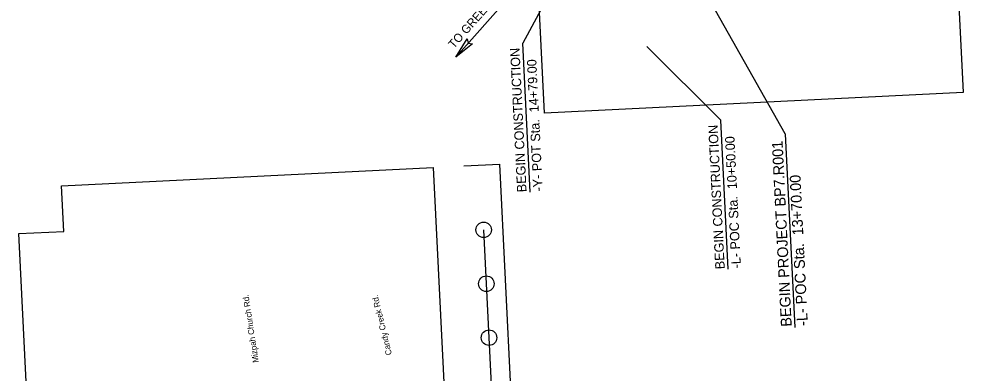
# Model space of a CAD drawing. Extents: x 1805231 to 1809482, y 908883 to 918297.
# Drawn here: x 1805232 to 1808728, y 912434 to 913747 of the extents above; entities that cross this region are included whole.
import ezdxf

# ---------------------------------------------------------------- set-up
doc = ezdxf.new("R2010")
doc.units = 0
for name, color, linetype in [('Default', 7, 'Continuous'), ('Old_Level_40', 7, 'Continuous'), ('Prop DSN Text', 7, 'Continuous'), ('Prop Horizontal Alignment Station Label', 7, 'Continuous'), ('Prop Leader Line Medium', 7, 'Continuous'), ('Prop Terminator CELL', 7, 'Continuous'), ('Scratch_Level_0', 7, 'Continuous')]:
    doc.layers.add(name, color=color, linetype=linetype)

msp = doc.modelspace()

# ---------------------------------------------------------------- linework, layer by layer
at = {"layer": 'Old_Level_40'}
for p in [(1806880, 913201.5), (1807095.1, 911542.9)]:
    msp.add_line(p, (1807012.5, 913208), dxfattribs=at)
at = {"layer": 'Prop DSN Text'}
msp.add_line((1806982.8, 912365.7), (1806953, 912965), dxfattribs=at)
for centre in [(1806953, 912965), (1806962.9, 912765.3), (1806972.9, 912565.5)]:
    msp.add_circle(centre, 28.8, dxfattribs=at)
at = {"layer": 'Prop Horizontal Alignment Station Label'}
for p, q in [((1807339.4, 914103.4), (1807097.7, 913656.9)), ((1808069, 913321.2), (1807740.1, 913904.3)), ((1807125.1, 913104.4), (1807097.7, 913656.9)), ((1807831.5, 913371.8), (1807556.7, 913643.8)), ((1807858.9, 912819.3), (1807831.5, 913371.8)), ((1808069, 913321.2), (1808104.6, 912602.7))]:
    msp.add_line(p, q, dxfattribs=at)
at = {"layer": 'Prop Leader Line Medium'}
msp.add_line((1806849.7, 913604.7), (1807106.1, 913893.9), dxfattribs=at)
at = {"layer": 'Prop Terminator CELL'}
msp.add_lwpolyline([(1806912.1, 913654.6), (1806849.7, 913604.7), (1806891.8, 913673.2), (1806895.6, 913656.4)], close=True, dxfattribs=at)
at = {"layer": 'Scratch_Level_0'}
for points in [[(1807178.4, 913396.6), (1807021.1, 916565.5), (1808571, 916642.5), (1808728.3, 913473.6)], [(1807168.8, 913438.8), (1807168.8, 913438.8), (1807168.8, 913438.8), (1807168.8, 913438.8)], [(1805306.3, 911454), (1805232, 912951), (1805398.3, 912959.3), (1805389.9, 913127.5), (1806765.8, 913195.8), (1806848.5, 911530.6)]]:
    msp.add_lwpolyline(points, close=True, dxfattribs=at)

# ---------------------------------------------------------------- texts
at = {"layer": 'Default'}
for s, rotation, p in [('Mizpah Church Rd.', 98.6024, (1806120.1, 912474.7)), ('Candy Creek Rd.', 103.4814, (1806613.3, 912503.5))]:
    msp.add_text(s, height=22.242, rotation=rotation, dxfattribs=at).set_placement(p)
at = {"layer": 'Prop Horizontal Alignment Station Label'}
for s, height, p in [('BEGIN CONSTRUCTION', 35, (1807112, 913105)), ('-Y- POT Sta.  14+79.00', 35, (1807172, 913107.9)), ('BEGIN CONSTRUCTION', 35, (1807845.8, 912819.8)), ('-L- POC Sta.  10+50.00', 35, (1807905.7, 912822.8)), ('BEGIN PROJECT BP7.R001', 40, (1808093.9, 912607)), ('-L- POC Sta.  13+70.00', 40, (1808153.6, 912610))]:
    msp.add_text(s, height=height, rotation=92.8422, dxfattribs=at).set_placement(p)
at = {"layer": 'Prop Leader Line Medium'}
msp.add_text('TO GREENSBORO', height=31.5, rotation=48.4457, dxfattribs=at).set_placement((1806842.6, 913634.5))

doc.saveas('drawing.dxf')
